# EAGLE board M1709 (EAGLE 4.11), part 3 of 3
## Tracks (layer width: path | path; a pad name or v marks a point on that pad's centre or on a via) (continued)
N$445 (continued)
  Bottom 0.381: E35.13 44.45,114.3 45.09,114.94 47.62,114.94 E16-307.1
N$446
  Bottom 0.381: E35.14 44.45,116.84 46.35,118.75 47.62,118.75 E16-308.1
N$447
  Bottom 0.381: E35.15 44.45,119.38 47.62,122.56 E16-309.1
N$448
  Bottom 0.381: E35.16 43.81,122.56 47.62,126.37 E16-310.1
N$449
  Bottom 0.381: C35.1 34.92,96.52 31.11,96.52 E16-311.1
N$450
  Bottom 0.381: C35.2 43.81,96.52 47.62,96.52 E16-312.1
N$451
  Bottom 0.381: E36.1 9.53,122.56 5.71,126.37 E16-313.1
N$452
  Bottom 0.381: E36.2 8.89,119.38 5.71,122.56 E16-314.1
N$453
  Bottom 0.381: E36.3 8.89,116.84 6.99,118.75 5.71,118.75 E16-315.1
N$454
  Bottom 0.381: E36.4 8.89,114.3 8.26,114.94 5.71,114.94 E16-316.1
N$455
  Bottom 0.381: E36.5 8.89,111.76 5.71,111.76 E16-317.1
N$456
  Bottom 0.381: E36.6 8.89,109.22 8.26,108.59 5.71,108.59 E16-318.1
N$457
  Bottom 0.381: E36.7 8.89,106.68 6.99,104.78 5.71,104.78 E16-319.1
N$458
  Bottom 0.381: E36.8 8.89,104.14 5.71,100.97 E16-320.1
N$459
  Bottom 0.381: E36.9 19.05,104.14 22.23,100.97 E16-321.1
N$460
  Bottom 0.381: E36.10 19.05,106.68 20.95,104.78 22.23,104.78 E16-322.1
N$461
  Bottom 0.381: E36.11 19.05,109.22 19.68,108.59 22.23,108.59 E16-323.1
N$462
  Bottom 0.381: E36.12 19.05,111.76 22.23,111.76 E16-324.1
N$463
  Bottom 0.381: E36.13 19.05,114.3 19.68,114.94 22.23,114.94 E16-325.1
N$464
  Bottom 0.381: E36.14 19.05,116.84 20.95,118.75 22.23,118.75 E16-326.1
N$465
  Bottom 0.381: E36.15 19.05,119.38 22.23,122.56 E16-327.1
N$466
  Bottom 0.381: E36.16 18.41,122.56 22.23,126.37 E16-328.1
N$467
  Bottom 0.381: C36.1 9.53,96.52 5.71,96.52 E16-329.1
N$468
  Bottom 0.381: C36.2 18.41,96.52 22.23,96.52 E16-330.1
N$469
  Bottom 0.381: E22.1 224.16,188.6 227.97,192.41 E16-331.1
N$470
  Bottom 0.381: E22.2 220.98,189.23 224.16,192.41 E16-332.1
N$471
  Bottom 0.381: E22.3 218.44,189.23 221.62,192.41 E16-333.1
N$472
  Bottom 0.381: E22.4 215.9,189.23 215.9,192.41 216.53,192.41 E16-334.1
N$473
  Bottom 0.381: E22.5 213.36,189.23 213.36,192.41 E16-335.1
N$474
  Bottom 0.381: E22.6 210.82,189.23 210.82,192.41 210.19,192.41 E16-336.1
N$475
  Bottom 0.381: E22.7 208.28,189.23 205.1,192.41 E16-337.1
N$476
  Bottom 0.381: E22.8 205.74,189.23 202.56,192.41 E16-338.1
N$477
  Bottom 0.381: E22.9 205.74,179.07 202.56,175.9 E16-339.1
N$478
  Bottom 0.381: E22.10 208.28,179.07 205.1,175.9 E16-340.1
N$479
  Bottom 0.381: E22.11 210.82,179.07 210.82,175.9 210.19,175.9 E16-341.1
N$480
  Bottom 0.381: E22.12 213.36,179.07 213.36,175.9 E16-342.1
N$481
  Bottom 0.381: E22.13 215.9,179.07 215.9,175.9 216.53,175.9 E16-343.1
N$482
  Bottom 0.381: E22.14 218.44,179.07 221.62,175.9 E16-344.1
N$483
  Bottom 0.381: E22.15 220.98,179.07 224.16,175.9 E16-345.1
N$484
  Bottom 0.381: E22.16 224.16,179.71 227.97,175.9 E16-346.1
N$485
  Bottom 0.381: C22.1 198.12,188.6 198.12,192.41 E16-347.1
N$486
  Bottom 0.381: C22.2 198.12,179.71 198.12,175.9 E16-348.1
N$487  (via drill 0.61)
  Top 0.381: v30.48,57.15 29.84,57.79 29.84,78.11 38.1,86.36 44.45,86.36 44.45,91.44 43.18,92.71 28.57,92.71 v28.57,90.17 | v6.99,61.6 6.35,60.96 6.35,45.72 5.08,44.45 SV9.1
  Bottom 0.381: v30.48,57.15 40.64,57.15 41.91,55.88 E12.15 | v28.57,90.17 25.4,87 15.88,87 11.43,82.55 8.89,82.55 6.99,80.65 v6.99,61.6
N$488  (via drill 0.61)
  Top 0.381: v30.48,53.34 27.94,50.8 v27.94,35.56
  Bottom 0.381: v30.48,53.34 31.75,54.61 36.83,54.61 38.1,53.34 41.91,53.34 E12.14 | v27.94,35.56 13.97,35.56 7.62,41.91 SV9.2
N$489  (via drill 0.61)
  Top 0.381: v48.26,50.17 49.53,48.9 v49.53,38.1
  Bottom 0.381: v48.26,50.17 45.09,50.17 44.45,50.8 E12.13 | v49.53,38.1 39.37,38.1 38.1,36.83 15.24,36.83 10.16,41.91 SV9.3
N$490  (via drill 0.61)
  Top 0.381: v39.37,39.37 39.37,44.45 44.45,44.45 45.09,45.09 45.09,46.36 43.81,47.63 E12.12
  Bottom 0.381: v39.37,39.37 38.1,38.1 22.23,38.1 19.68,40.64 13.97,40.64 12.7,41.91 SV9.4
N$491  (via drill 0.61)
  Top 0.381: v40.01,47.63 41.91,45.72 E12.11
  Bottom 0.381: v40.01,47.63 39.37,46.99 17.78,46.99 15.24,44.45 SV9.5
N$492
  Bottom 0.381: E12.10 41.91,43.18 40.64,44.45 24.77,44.45 23.5,45.72 19.05,45.72 17.78,44.45 SV9.6
N$493
  Bottom 0.381: E12.9 41.91,40.64 38.1,40.64 36.83,39.37 22.86,39.37 20.32,41.91 SV9.7
N$494
  Bottom 0.381: E12.7 34.29,43.18 23.5,43.18 SV9.8
N$495  (via drill 0.61)
  Top 0.381: v26.67,74.3 24.13,71.76 v24.13,60.96
  Bottom 0.381: v26.67,74.3 32.38,80.01 40.64,80.01 41.91,78.74 E13.15 | v24.13,60.96 19.05,55.88 8.89,55.88 5.08,52.07 SV10.1
N$496  (via drill 0.61)
  Top 0.381: v39.37,20.96 39.37,22.23 36.83,24.77 36.83,29.85 45.09,38.1 45.09,42.55 46.35,43.82 46.35,73.03 43.81,75.57 E13.14 | v14.61,20.96 14.61,30.48 8.89,36.2 8.89,48.26 7.62,49.53 SV10.2
  Bottom 0.381: v14.61,20.96 v39.37,20.96
N$497  (via drill 0.61)
  Top 0.381: v31.11,66.04 31.11,69.22 34.29,72.39 33.66,73.03 33.66,74.3 34.29,74.93 33.66,75.57 33.66,77.47 38.1,77.47 41.91,73.66 E13.13 | v12.06,64.77 8.89,64.77 8.89,62.23 8.26,61.6 8.26,53.98 10.16,52.07 SV10.3
  Bottom 0.381: v31.11,66.04 29.21,64.14 18.41,64.14 17.78,64.77 v12.06,64.77
N$498  (via drill 0.61)
  Top 0.381: v31.75,64.14 31.75,46.99 36.83,46.99 38.73,48.9 38.73,66.68 42.55,70.49 E13.12 | v12.06,63.5 12.06,51.44 SV10.4
  Bottom 0.381: v31.75,64.14 29.84,62.23 19.05,62.23 17.78,63.5 v12.06,63.5
N$499  (via drill 0.61)
  Top 0.381: v40.01,52.07 40.01,65.41 42.55,67.95 E13.11 | v25.4,57.79 v25.4,52.71
  Bottom 0.381: v40.01,52.07 26.04,52.07 v25.4,52.71 | v25.4,57.79 22.23,54.61 17.78,54.61 15.24,52.07 SV10.5
N$500  (via drill 0.61)
  Top 0.381: v24.13,52.71 22.86,53.98 21.59,53.98 v21.59,53.34
  Bottom 0.381: v24.13,52.71 24.13,53.34 30.48,59.69 35.56,59.69 41.91,66.04 E13.10 | v21.59,53.34 19.05,53.34 17.78,52.07 SV10.6
N$501  (via drill 0.61)
  Top 0.381: v41.27,52.07 41.27,61.6 42.55,62.87 E13.9
  Bottom 0.381: v41.27,52.07 41.27,49.53 24.77,49.53 23.5,48.26 21.59,48.26 20.32,49.53 SV10.7
N$502
  Bottom 0.381: E13.7 34.92,65.41 22.86,53.34 22.86,52.07 SV10.8
N$503  (via drill 0.61)
  Top 0.381: v54.61,64.77 v54.61,79.38 | v130.81,83.82 130.81,61.6 135.89,56.52 E5.2
  Bottom 0.381: v54.61,64.77 49.53,59.69 41.91,59.69 40.64,58.42 36.83,58.42 E12.1 | v54.61,79.38 66.67,91.44 123.19,91.44 v130.81,83.82
N$504  (via drill 0.61)
  Top 0.381: v50.8,49.53 54.61,45.72 v54.61,34.29 | v117.47,35.56 v132.08,50.17
  Bottom 0.381: v50.8,49.53 45.72,54.61 38.1,54.61 36.83,55.88 E12.2 | v54.61,34.29 66.67,34.29 67.94,35.56 v117.47,35.56 | v132.08,50.17 132.72,50.8 135.25,50.8 E5.4
N$505  (via drill 0.61)
  Top 0.381: v33.66,60.96 33.66,55.25 34.92,53.98 E12.3 | v125.73,62.23 134.62,53.34 134.62,47.63 135.89,46.36 E5.6
  Bottom 0.381: v33.66,60.96 34.92,62.23 36.83,62.23 41.91,67.31 100.97,67.31 106.05,62.23 v125.73,62.23
N$506  (via drill 0.61)
  Top 0.381: v73.03,69.85 73.03,69.22 85.72,56.52 E9.2 | v39.37,69.85 37.47,71.76 37.47,74.3 36.2,75.57 E13.3
  Bottom 0.381: v39.37,69.85 v73.03,69.85
N$507  (via drill 0.61)
  Top 0.381: v48.9,74.93 50.8,74.93 50.8,51.44 56.52,45.72 56.52,39.37 57.15,38.74 57.15,30.48 57.78,29.85 71.12,29.85 71.12,35.56 85.72,50.17 E9.4
  Bottom 0.381: v48.9,74.93 40.64,74.93 36.83,78.74 E13.2
N$508  (via drill 0.61)
  Top 0.381: v57.78,43.18 57.78,48.26 52.07,53.98 52.07,77.47 41.91,77.47 41.27,78.11 41.27,81.28 36.83,81.28 E13.1
  Bottom 0.381: v57.78,43.18 57.78,39.37 62.23,39.37 67.31,44.45 71.12,44.45 72.39,45.72 85.09,45.72 E9.6
N$509  (via drill 0.61)
  Top 0.381: v113.67,60.96 113.67,50.17 112.39,48.9 E7.4 | v149.22,58.42 152.4,55.25 v152.4,48.26 | v59.69,35.56 64.14,40.01 v64.14,58.42
  Bottom 0.381: E14.4 9.53,75.57 9.53,74.3 E14.5 9.53,73.03 8.26,71.76 8.26,62.87 10.79,62.87 12.06,61.6 12.06,57.15 8.26,57.15 3.81,52.71 3.81,34.29 43.81,34.29 45.09,35.56 v59.69,35.56 | E3.7 161.93,41.28 161.93,42.55 E3.6 161.29,43.18 157.48,43.18 v152.4,48.26 | v149.22,58.42 146.69,60.96 v113.67,60.96 66.67,60.96 v64.14,58.42
N$510  (via drill 0.61)
  Top 0.381: v156.84,34.29 156.84,42.55 161.93,47.63 E3.4
  Bottom 0.381: v156.84,34.29 156.21,33.66 128.27,33.66 114.94,20.32 80.64,20.32 79.38,21.59 59.05,21.59 57.78,20.32 48.9,20.32 45.09,24.13 41.91,24.13 40.01,22.23 10.16,22.23 1.27,31.12 1.27,60.33 9.53,60.33 #17.1
N$511  (via drill 0.61)
  Top 0.381: v162.56,36.83 160.66,38.74 160.66,43.82 161.93,45.09 E3.5 | v76.83,32.39 v78.74,34.29 | v18.41,33.02 16.51,34.93 16.51,59.69 17.14,60.33 #18.1
  Bottom 0.381: v162.56,36.83 161.29,35.56 119.38,35.56 118.11,34.29 v78.74,34.29 | v76.83,32.39 71.75,27.31 52.07,27.31 51.44,26.67 48.9,26.67 48.26,27.31 33.02,27.31 32.38,26.67 24.77,26.67 v18.41,33.02
N$512  (via drill 0.61)
  Top 0.381: v117.47,44.45 124.46,44.45 v124.46,63.5 | v158.75,57.15 160.66,55.25 160.66,52.71 161.93,51.44 E3.3
  Bottom 0.381: v117.47,44.45 114.3,44.45 113.03,45.72 E7.5 | v124.46,63.5 143.51,63.5 144.78,62.23 153.03,62.23 158.12,57.15 v158.75,57.15
N$513
  Bottom 0.381: E14.15 17.14,81.92 15.88,83.19 15.88,85.73 25.4,85.73 27.94,88.27 29.84,88.27 SV11.1
N$514  (via drill 0.61)
  Top 0.381: v27.3,81.92 33.02,87.63 SV11.2
  Bottom 0.381: v27.3,81.92 22.23,81.92 19.05,78.74 E14.14
N$515  (via drill 0.61)
  Top 0.381: v25.4,84.46 25.4,83.82 18.41,76.84 E14.13
  Bottom 0.381: v25.4,84.46 27.3,86.36 34.29,86.36 35.56,87.63 SV11.3
N$516  (via drill 0.61)
  Top 0.381: v15.88,90.17 15.88,75.57 17.14,74.3 E14.12
  Bottom 0.381: v15.88,90.17 17.14,91.44 36.83,91.44 38.1,90.17 SV11.4
N$517  (via drill 0.61)
  Top 0.381: v14.61,87.63 14.61,74.3 17.14,71.76 E14.11
  Bottom 0.381: v14.61,87.63 14.61,92.71 38.1,92.71 40.64,90.17 SV11.5
N$518  (via drill 0.61)
  Top 0.381: v27.94,69.85 28.57,70.49 28.57,78.74 36.83,87 36.83,90.81 37.47,91.44 43.18,91.44 43.18,90.17 SV11.6
  Bottom 0.381: v27.94,69.85 20.32,69.85 19.05,68.58 E14.10
N$519  (via drill 0.61)
  Top 0.381: v20.95,65.41 21.59,66.04 21.59,78.74 27.3,84.46 27.3,92.71 28.57,93.98 45.72,93.98 45.72,90.17 SV11.7
  Bottom 0.381: v20.95,65.41 19.68,65.41 19.05,66.04 E14.9
N$520  (via drill 0.61)
  Top 0.381: v8.26,90.81 8.26,70.49 9.53,69.22 E14.7
  Bottom 0.381: v8.26,90.81 11.43,93.98 40.01,93.98 42.55,91.44 46.99,91.44 48.26,90.17 SV11.8
N$521  (via drill 0.61)
  Top 0.381: v109.86,46.99 109.86,45.09 111.12,43.82 E7.6 | v95.25,82.55 95.89,81.92 95.89,45.09 94.61,43.82 E9.10
  Bottom 0.381: v109.86,46.99 92.08,46.99 92.08,45.09 93.34,43.82 E9.10 | v95.25,82.55 80.01,82.55 74.3,88.27 #27_IO_PAUSE.1
N$522  (via drill 0.61)
  Top 0.381: v103.5,83.82 105.41,81.92 105.41,70.49 109.86,66.04 109.86,55.25 111.12,53.98 E7.2
  Bottom 0.381: 111.12,52.07 111.12,52.71 E7.2 | 111.12,52.07 111.12,51.44 E7.3 | 111.12,52.07 160.02,52.07 161.29,53.34 E3.2 | v103.5,83.82 82.55,83.82 78.11,88.27 #28_SELECT.1
N$523
  Top 0.381: E9.14 93.34,53.98 92.08,55.25 92.08,62.23 85.09,69.22 85.09,88.27 #30_BINIT\.1
N$524
  Top 0.381: E9.12 93.34,48.9 90.81,51.44 90.81,62.23 81.92,71.12 81.92,88.27 #29_BTP3\.1
N$525  (via drill 0.61)
  Top 0.381: v87.63,92.71 87.63,73.03 86.36,71.76 R6.2
  Bottom 0.381: R6.2 87,71.12 88.27,69.85 89.53,69.85 90.81,71.12 R5.1 | v87.63,92.71 87,93.35 41.91,93.35 36.83,98.43 13.97,98.43 6.99,91.44 6.99,89.54 9.53,89.54 3V1.1
N$526  (via drill 0.61)
  Top 0.381: v92.71,92.71 92.71,73.03 93.98,71.76 R7.1 | v54.61,94.62 54.61,95.25 51.44,98.43 19.05,98.43 19.05,90.17 18.41,89.54 3V2.1
  Bottom 0.381: R8.2 89.53,71.12 90.81,72.39 92.08,72.39 93.34,71.12 R7.1 | v92.71,92.71 90.81,94.62 v54.61,94.62
NOT_LAST_TR\
  Top 0.381: BUS59.1 95.89,27.94 96.52,27.31 96.52,23.5 97.16,22.86 97.16,13.97 U$2.CM1
OVERFLOW\  (via drill 0.61)
  Top 0.381: v168.28,15.24 168.28,24.77 BUS45.1
  Bottom 0.381: v168.28,15.24 168.28,13.97 U$2.BJ2
SKIP\  (via drill 0.61)
  Top 0.381: v116.2,30.48 116.2,50.17 118.75,52.71 E7.13 | U$2.CS1 84.45,13.97 84.45,24.13 83.19,25.4 83.19,27.94 BUS55.1
  Bottom 0.381: v116.2,30.48 112.39,30.48 111.76,29.85 109.22,29.85 108.58,30.48 106.05,30.48 105.41,29.85 102.87,29.85 102.23,30.48 99.69,30.48 99.06,29.85 96.52,29.85 95.89,30.48 93.34,30.48 89.53,26.67 87,26.67 85.72,27.94 83.19,27.94 BUS55.1
TP1  (via drill 0.61)
  Top 0.381: v117.47,15.24 117.47,24.77 BUS80.1
  Bottom 0.381: v117.47,15.24 117.47,13.97 U$2.CD2
TP2  (via drill 0.61)
  Top 0.381: v114.3,15.24 114.3,21.59 BUS79.1
  Bottom 0.381: v114.3,15.24 114.3,13.97 U$2.CE2
TP3  (via drill 0.61)
  Top 0.381: v106.68,50.17 108.58,48.26 108.58,30.48 109.86,29.21 109.86,26.67 108.58,25.4 108.58,22.86 BUS77.1 107.95,21.59 v107.95,17.78
  Bottom 0.381: v106.68,50.17 95.89,50.17 95.25,50.8 E9.13 | v107.95,17.78 107.95,13.97 U$2.CH2
TP4  (via drill 0.61)
  Top 0.381: v104.78,17.78 104.78,24.77 BUS76.1
  Bottom 0.381: v104.78,17.78 104.78,13.97 U$2.CJ2
TS1\  (via drill 0.61)
  Top 0.381: v101.6,17.78 101.6,21.59 BUS75.1
  Bottom 0.381: v101.6,17.78 101.6,13.97 U$2.CK2
TS2\  (via drill 0.61)
  Top 0.381: v98.42,17.78 98.42,24.77 BUS74.1
  Bottom 0.381: v98.42,17.78 98.42,13.97 U$2.CL2
TS3\  (via drill 0.61)
  Top 0.381: v95.25,17.78 95.25,21.59 BUS73.1
  Bottom 0.381: v95.25,17.78 95.25,13.97 U$2.CM2
TS4\  (via drill 0.61)
  Top 0.381: v88.9,15.24 88.9,21.59 BUS71.1
  Bottom 0.381: v88.9,15.24 88.9,13.97 U$2.CP2
VCC  (via drill 0.61)
  Top 0.381: v127,19.05 127,21.59 BUS82.1 | v118.75,58.42 118.75,56.52 E7.14 | C40.+ 46.35,34.29 46.99,34.93 46.99,43.18 48.26,44.45 48.26,47.63 C12.1 | E4.8 170.81,65.41 172.72,63.5 172.72,62.23 180.34,54.61 180.34,51.44 182.88,48.9 C1.1 | v190.5,17.78 190.5,21.59 BUS51.1 | v170.81,32.39 170.81,40.01 E3.8
  Bottom 0.381: C7.1 107.31,48.26 108.58,49.53 130.18,49.53 131.44,48.26 C5.1 132.72,48.26 133.99,49.53 155.57,49.53 156.84,48.26 C3.1 157.48,47.63 160.66,44.45 175.26,44.45 | v127,19.05 127,13.97 U$2.CA2 | 118.75,59.69 141.6,59.69 142.88,58.42 E5.16 | 118.75,59.69 96.52,59.69 95.25,58.42 E9.16 | 118.75,59.69 v118.75,58.42 | U$2.AA2 260.35,13.97 260.35,21.59 BUS24.1 259.71,22.86 259.71,41.91 C15.+ 257.81,42.55 255.91,40.64 242.57,40.64 | E4.8 171.45,66.04 174.62,66.04 R3.2 | 175.26,44.45 179.07,48.26 182.25,48.26 C1.1 182.88,47.63 182.88,39.37 191.13,39.37 | 175.26,44.45 171.45,40.64 E3.8 | 191.13,39.37 191.13,40.64 194.31,40.64 E1.8 194.94,41.28 193.68,42.55 193.68,44.45 200.03,44.45 C39.+ 201.93,42.55 203.84,40.64 242.57,40.64 | 191.13,39.37 191.13,22.86 BUS51.1 | v190.5,17.78 190.5,13.97 U$2.BA2 | E14.6 11.43,71.12 12.7,72.39 20.95,72.39 22.23,73.66 C14.1 23.5,73.66 26.04,71.12 31.75,71.12 34.29,68.58 E13.6 36.2,69.22 39.37,72.39 50.16,72.39 | 51.44,74.3 52.07,73.66 | 51.44,74.3 44.45,81.28 E13.16 41.91,81.28 40.01,83.19 19.68,83.19 19.05,83.82 E14.16 | 52.07,73.66 55.24,73.66 C11.1 | 66.04,80.01 67.31,81.28 E11.14 | 66.04,80.01 57.15,80.01 51.44,74.3 | 50.16,72.39 51.44,73.66 52.07,73.66 | 50.16,72.39 48.9,71.12 C13.1 | 66.04,80.01 89.53,80.01 90.81,81.28 R5.2 92.08,81.28 93.34,81.28 R7.2 94.61,81.28 95.89,81.28 97.16,82.55 113.03,82.55 114.3,81.28 118.11,81.28 E8.14 120.65,81.28 130.18,81.28 131.44,82.55 142.24,82.55 143.51,81.28 E6.14 146.05,81.28 147.32,82.55 182.25,82.55 | C38.+ 85.09,174.63 166.37,174.63 C37.+ 168.91,175.9 170.81,177.8 191.13,177.8 206.38,162.56 206.38,132.72 222.88,132.72 227.97,127.64 227.97,71.76
  Bottom 0.381: C2.1 200.03,73.66 198.75,74.93 186.06,74.93 182.88,71.76 R2.2 182.25,71.12 178.44,74.93 | C8.1 107.31,73.66 108.58,74.93 127.64,74.93 131.44,71.12 R1.2 132.72,71.12 133.99,72.39 147.96,72.39 149.22,73.66 C6.1 150.5,73.66 156.84,73.66 C4.1 158.12,73.66 159.38,74.93 178.44,74.93 | 182.25,82.55 193.04,82.55 194.31,81.28 E2.14 196.85,81.28 212.72,81.28 222.88,71.12 R4.2 223.52,71.76 227.97,71.76 | 182.25,82.55 178.44,78.74 178.44,74.93 | 242.57,40.64 242.57,55.25 233.04,55.25 227.97,60.33 227.97,71.76
  pour Bottom (isolate 0.406): 0,19.05 265.43,19.05 265.43,214.63 0,214.63

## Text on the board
Top: M1709 IMNIBUS Interface Foundation
Bottom: M1709 IMNIBUS Interface Foundation
tValues: M1709 IMNIBUS Interface Foundation | 28 | 30 | 27 | 29 | 17 | 18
